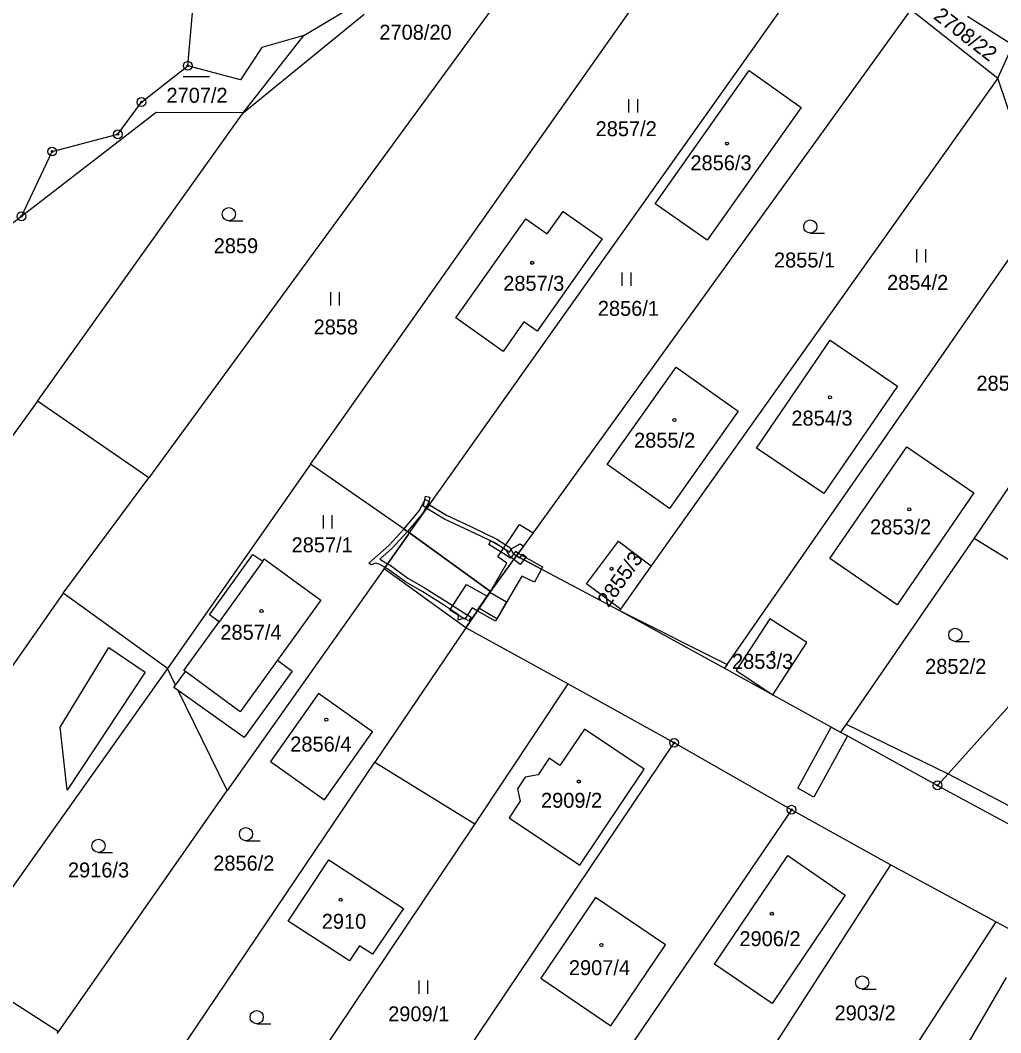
# Model space of a CAD drawing. Extents: x -755819 to -753140, y -1169796 to -1166000.
# Drawn here: x -754138.8 to -754027.3, y -1168813.4 to -1168698.3 of the extents above; entities that cross this region are included whole.
import ezdxf

# ---------------------------------------------------------------- set-up
doc = ezdxf.new("R2010")
doc.units = 0
for name, color, linetype in [('Vrstva 1', 7, 'Continuous'), ('Vrstva 16', 7, 'Continuous'), ('Vrstva 18', 7, 'Continuous'), ('Vrstva 19', 7, 'Continuous'), ('Vrstva 24', 7, 'Continuous'), ('Vrstva 25', 7, 'Continuous'), ('Vrstva 27', 7, 'Continuous'), ('Vrstva 4', 7, 'Continuous'), ('Vrstva 6', 7, 'Continuous')]:
    doc.layers.add(name, color=color, linetype=linetype)

msp = doc.modelspace()

# ---------------------------------------------------------------- linework, layer by layer
at = {"layer": 'Vrstva 1'}
for p, q in [((-754105.8, -1168748.75), (-754061.85, -1168686.4)), ((-754119.75, -1168703.46), (-754118.3, -1168687.42)), ((-754094.54, -1168756.59), (-754046.75, -1168689.25)), ((-754081.72, -1168692.26), (-754124.16, -1168750.33)), ((-754037.53, -1168697.06), (-754082.38, -1168759.2)), ((-754037.53, -1168697.06), (-754027.62, -1168704.86)), ((-754113.45, -1168708.82), (-754099.68, -1168697.61)), ((-754025.93, -1168701.12), (-754031.1, -1168697.87)), ((-754125.01, -1168707.59), (-754119.75, -1168703.46)), ((-754066.6, -1168719.15), (-754055.91, -1168704.01)), ((-754055.91, -1168704.01), (-754049.98, -1168708.21)), ((-754027.62, -1168704.86), (-754053.75, -1168741.61)), ((-754022.59, -1168719.93), (-754027.62, -1168704.86)), ((-754127.7, -1168711.26), (-754125.01, -1168707.59)), ((-754123.33, -1168708.78), (-754138.66, -1168720.59)), ((-754136.85, -1168741.61), (-754113.45, -1168708.82)), ((-754113.45, -1168708.82), (-754123.33, -1168708.78)), ((-754049.98, -1168708.21), (-754060.68, -1168723.31)), ((-754135.16, -1168713.21), (-754127.7, -1168711.26)), ((-754138.66, -1168720.59), (-754135.16, -1168713.21)), ((-754060.68, -1168723.31), (-754066.6, -1168719.15)), ((-754078.89, -1168722.58), (-754077.07, -1168720.02)), ((-754077.07, -1168720.02), (-754072.64, -1168723.16)), ((-754022.59, -1168719.93), (-754042.2, -1168748.18)), ((-754138.66, -1168720.59), (-754146.02, -1168726.26)), ((-754089.25, -1168732.14), (-754081.32, -1168720.86)), ((-754081.32, -1168720.86), (-754078.89, -1168722.58)), ((-754072.64, -1168723.16), (-754080.01, -1168733.66)), ((-754011.92, -1168729.81), (-754030.32, -1168757.19)), ((-754083.88, -1168735.95), (-754089.25, -1168732.14)), ((-754081.52, -1168732.59), (-754083.88, -1168735.95)), ((-754080.01, -1168733.66), (-754081.52, -1168732.59)), ((-754055.06, -1168746.94), (-754046.7, -1168734.65)), ((-754046.7, -1168734.65), (-754039.06, -1168739.88)), ((-754072.04, -1168748.81), (-754064.22, -1168737.74)), ((-754064.22, -1168737.74), (-754057.16, -1168742.74)), ((-754039.06, -1168739.88), (-754047.44, -1168752.12)), ((-754136.85, -1168741.61), (-754192.93, -1168819.06)), ((-754124.16, -1168750.33), (-754136.85, -1168741.61)), ((-754053.75, -1168741.61), (-754067.04, -1168760.31)), ((-754057.16, -1168742.74), (-754064.98, -1168753.81)), ((-754047.44, -1168752.12), (-754055.06, -1168746.94)), ((-754046.75, -1168759.51), (-754037.99, -1168746.78)), ((-754037.99, -1168746.78), (-754030.36, -1168752.02)), ((-754105.8, -1168748.75), (-754122.05, -1168772)), ((-754094.54, -1168756.59), (-754105.8, -1168748.75)), ((-754064.98, -1168753.81), (-754072.04, -1168748.81)), ((-754058.42, -1168771.55), (-754042.2, -1168748.18)), ((-754133.92, -1168763.44), (-754124.16, -1168750.33)), ((-754030.36, -1168752.02), (-754039.1, -1168764.78)), ((-754094.54, -1168756.59), (-754115.25, -1168785.86)), ((-754085.34, -1168763.23), (-754094.54, -1168756.59)), ((-754030.32, -1168757.19), (-754044.9, -1168778.35)), ((-754030.32, -1168757.19), (-754020.27, -1168763.43)), ((-754074.39, -1168762.36), (-754070.76, -1168757.54)), ((-754070.76, -1168757.54), (-754067.04, -1168760.31)), ((-754117.27, -1168765.9), (-754112.33, -1168759.03)), ((-754112.33, -1168759.03), (-754111.23, -1168759.79)), ((-754111.23, -1168759.79), (-754111.05, -1168759.55)), ((-754111.05, -1168759.55), (-754104.62, -1168764.23)), ((-754085.34, -1168763.23), (-754082.38, -1168759.2)), ((-754082.38, -1168759.2), (-754070.67, -1168765.41)), ((-754039.1, -1168764.78), (-754046.75, -1168759.51)), ((-754067.04, -1168760.31), (-754070.56, -1168765.26)), ((-754070.56, -1168765.26), (-754074.39, -1168762.36)), ((-754133.92, -1168763.44), (-754179.64, -1168828.63)), ((-754122.05, -1168772), (-754133.92, -1168763.44)), ((-754104.62, -1168764.23), (-754109.56, -1168771.07)), ((-754088.14, -1168767.36), (-754085.34, -1168763.23)), ((-754070.56, -1168765.26), (-754070.67, -1168765.41)), ((-754116.18, -1168766.68), (-754117.27, -1168765.9)), ((-754070.67, -1168765.41), (-754058.72, -1168771.98)), ((-754053.56, -1168766.35), (-754057.4, -1168772.22)), ((-754049.35, -1168769.06), (-754053.56, -1168766.35)), ((-754016.79, -1168765.59), (-754033.3, -1168783.96)), ((-754120.18, -1168772.24), (-754116.18, -1168766.68)), ((-754088.14, -1168767.36), (-754098.48, -1168782.67)), ((-754076.53, -1168773.73), (-754088.14, -1168767.36)), ((-754053.22, -1168775), (-754049.35, -1168769.06)), ((-754109.56, -1168771.07), (-754107.86, -1168772.31)), ((-754122.05, -1168772), (-754146.05, -1168805.82)), ((-754121.13, -1168773.88), (-754122.05, -1168772)), ((-754120.02, -1168772.35), (-754120.18, -1168772.24)), ((-754058.42, -1168771.55), (-754058.72, -1168771.98)), ((-754058.72, -1168771.98), (-754053.22, -1168775)), ((-754057.4, -1168772.22), (-754053.22, -1168775)), ((-754121.13, -1168773.88), (-754120.02, -1168772.35)), ((-754107.86, -1168772.31), (-754113.34, -1168779.84)), ((-754121.32, -1168774.15), (-754121.13, -1168773.88)), ((-754120.82, -1168774.51), (-754121.32, -1168774.15)), ((-754115.25, -1168785.86), (-754120.82, -1168774.51)), ((-754113.34, -1168779.84), (-754120.82, -1168774.51)), ((-754076.53, -1168773.73), (-754087.1, -1168789.68)), ((-754064.45, -1168780.45), (-754076.53, -1168773.73)), ((-754104.87, -1168774.84), (-754110.34, -1168782.59)), ((-754098.74, -1168779.22), (-754104.87, -1168774.84)), ((-754053.22, -1168775), (-754045.51, -1168779.24)), ((-754074.64, -1168778.89), (-754077.43, -1168783.04)), ((-754067.84, -1168783.44), (-754074.64, -1168778.89)), ((-754044.9, -1168778.35), (-754045.51, -1168779.24)), ((-754104.2, -1168786.94), (-754098.74, -1168779.22)), ((-754045.51, -1168779.24), (-754044.73, -1168779.67)), ((-754044.73, -1168779.67), (-754034.5, -1168785.29)), ((-754101.73, -1168835.9), (-754064.45, -1168780.45)), ((-754051.1, -1168788.06), (-754064.45, -1168780.45)), ((-754110.34, -1168782.59), (-754104.2, -1168786.94)), ((-754078.67, -1168782.21), (-754079.92, -1168784.08)), ((-754077.43, -1168783.04), (-754078.67, -1168782.21)), ((-754123.7, -1168820.03), (-754098.48, -1168782.67)), ((-754075.17, -1168794.38), (-754067.84, -1168783.44)), ((-754081.39, -1168784.35), (-754082.27, -1168785.67)), ((-754079.92, -1168784.08), (-754081.39, -1168784.35)), ((-754033.3, -1168783.96), (-754034.5, -1168785.29)), ((-754134.46, -1168813.33), (-754115.25, -1168785.86)), ((-754082.27, -1168785.67), (-754081.96, -1168787.1)), ((-754034.5, -1168785.29), (-754022.41, -1168791.86)), ((-754081.96, -1168787.1), (-754083.22, -1168788.98)), ((-754051.1, -1168788.06), (-754088.9, -1168843.53)), ((-754039.84, -1168794.33), (-754051.1, -1168788.06)), ((-754083.22, -1168788.98), (-754075.17, -1168794.38)), ((-754087.1, -1168789.68), (-754114.82, -1168830.95)), ((-754108.33, -1168800.74), (-754103.69, -1168793.75)), ((-754103.69, -1168793.75), (-754095.23, -1168799.29)), ((-754059.87, -1168805.63), (-754051.5, -1168793.28)), ((-754051.5, -1168793.28), (-754045, -1168797.79)), ((-754039.84, -1168794.33), (-754075.63, -1168849.92)), ((-754027.85, -1168800.8), (-754039.84, -1168794.33)), ((-754073.38, -1168798.03), (-754079.6, -1168807.22)), ((-754065.41, -1168803.43), (-754073.38, -1168798.03)), ((-754045, -1168797.79), (-754053.3, -1168810.08)), ((-754095.23, -1168799.29), (-754098.73, -1168804.47)), ((-754101.34, -1168805.26), (-754108.33, -1168800.74)), ((-754027.85, -1168800.8), (-754051.69, -1168837.64)), ((-754013.92, -1168808.37), (-754027.85, -1168800.8)), ((-754100.21, -1168803.52), (-754101.34, -1168805.26)), ((-754098.73, -1168804.47), (-754100.21, -1168803.52)), ((-754071.63, -1168812.62), (-754065.41, -1168803.43)), ((-754053.3, -1168810.08), (-754059.87, -1168805.63)), ((-754134.46, -1168813.33), (-754146.05, -1168805.82)), ((-754079.6, -1168807.22), (-754071.63, -1168812.62)), ((-754031.7, -1168815.81), (-754026.65, -1168807.13)), ((-754134.59, -1168813.51), (-754134.46, -1168813.33))]:
    msp.add_line(p, q, dxfattribs=at)
at = {"layer": 'Vrstva 24'}
for centre, radius in [((-754119.75, -1168703.46), 0.5), ((-754119.75, -1168703.46), 0.1), ((-754125.01, -1168707.59), 0.5), ((-754125.01, -1168707.59), 0.1), ((-754127.7, -1168711.26), 0.5), ((-754127.7, -1168711.26), 0.1), ((-754135.16, -1168713.21), 0.5), ((-754135.16, -1168713.21), 0.1), ((-754138.66, -1168720.59), 0.5), ((-754138.66, -1168720.59), 0.1), ((-754064.45, -1168780.45), 0.5), ((-754064.45, -1168780.45), 0.1), ((-754034.5, -1168785.29), 0.5), ((-754034.5, -1168785.29), 0.1), ((-754051.1, -1168788.06), 0.5), ((-754051.1, -1168788.06), 0.1)]:
    msp.add_circle(centre, radius, dxfattribs=at)
at = {"layer": 'Vrstva 25'}
for p, q in [((-754120.27, -1168704.69), (-754117.27, -1168704.69)), ((-754069.58, -1168708.78), (-754069.58, -1168707.28)), ((-754068.58, -1168708.78), (-754068.58, -1168707.28)), ((-754115.07, -1168721.09), (-754113.47, -1168721.09)), ((-754048.96, -1168722.5), (-754047.36, -1168722.5)), ((-754036.84, -1168725.83), (-754036.84, -1168724.33)), ((-754035.84, -1168725.83), (-754035.84, -1168724.33)), ((-754070.34, -1168728.47), (-754070.34, -1168726.97)), ((-754069.34, -1168728.47), (-754069.34, -1168726.97)), ((-754103.49, -1168730.71), (-754103.49, -1168729.21)), ((-754102.49, -1168730.71), (-754102.49, -1168729.21)), ((-754104.32, -1168756.07), (-754104.32, -1168754.57)), ((-754103.32, -1168756.07), (-754103.32, -1168754.57)), ((-754032.47, -1168768.92), (-754030.87, -1168768.92)), ((-754113.13, -1168791.58), (-754111.53, -1168791.58)), ((-754129.9, -1168792.91), (-754128.3, -1168792.91)), ((-754093.44, -1168808.99), (-754093.44, -1168807.49)), ((-754092.44, -1168808.99), (-754092.44, -1168807.49)), ((-754043.07, -1168808.45), (-754041.47, -1168808.45)), ((-754111.91, -1168812.4), (-754110.31, -1168812.4))]:
    msp.add_line(p, q, dxfattribs=at)
for centre, radius in [((-754058.42, -1168712.31), 0.175), ((-754115.07, -1168720.34), 0.75), ((-754048.96, -1168721.75), 0.75), ((-754080.59, -1168725.87), 0.175), ((-754046.72, -1168741.17), 0.175), ((-754064.42, -1168743.74), 0.175), ((-754037.71, -1168753.91), 0.175), ((-754071.56, -1168760.67), 0.175), ((-754111.36, -1168765.47), 0.175), ((-754032.47, -1168768.17), 0.75), ((-754053.23, -1168770.22), 0.175), ((-754104, -1168777.82), 0.175), ((-754075.28, -1168784.85), 0.175), ((-754113.13, -1168790.83), 0.75), ((-754129.9, -1168792.16), 0.75), ((-754102.36, -1168798.3), 0.175), ((-754053.33, -1168799.89), 0.175), ((-754072.72, -1168803.44), 0.175), ((-754043.07, -1168807.7), 0.75), ((-754111.91, -1168811.65), 0.75)]:
    msp.add_circle(centre, radius, dxfattribs=at)
at = {"layer": 'Vrstva 27'}
for p, q in [((-754092.95, -1168753.54), (-754092.73, -1168752.42)), ((-754092.73, -1168752.42), (-754092.24, -1168752.51)), ((-754092.24, -1168752.51), (-754092.39, -1168753.3)), ((-754093.45, -1168754.07), (-754092.75, -1168752.78)), ((-754092.31, -1168753.02), (-754093.03, -1168754.35)), ((-754092.55, -1168753.79), (-754092.95, -1168753.54)), ((-754092.75, -1168752.78), (-754092.31, -1168753.02)), ((-754092.26, -1168753.38), (-754092.55, -1168753.79)), ((-754092.55, -1168753.79), (-754092.26, -1168753.38)), ((-754090.55, -1168755.02), (-754092.55, -1168753.79)), ((-754092.39, -1168753.3), (-754092.26, -1168753.38)), ((-754092.26, -1168753.38), (-754090.31, -1168754.58)), ((-754095.18, -1168756.15), (-754093.45, -1168754.07)), ((-754093.03, -1168754.35), (-754094.77, -1168756.43)), ((-754087.71, -1168756.35), (-754090.55, -1168755.02)), ((-754090.31, -1168754.58), (-754087.49, -1168755.89)), ((-754096.86, -1168757.97), (-754095.18, -1168756.15)), ((-754095.18, -1168756.15), (-754094.77, -1168756.43)), ((-754094.77, -1168756.43), (-754095.18, -1168756.15)), ((-754087.49, -1168755.89), (-754084.59, -1168757.29)), ((-754084.5, -1168759.29), (-754082.02, -1168755.61)), ((-754082.02, -1168755.61), (-754080.47, -1168756.56)), ((-754097.43, -1168760.67), (-754094.54, -1168756.59)), ((-754094.77, -1168756.43), (-754096.52, -1168758.33)), ((-754094.54, -1168756.59), (-754085.34, -1168763.23)), ((-754084.83, -1168757.73), (-754087.71, -1168756.35)), ((-754084.59, -1168757.29), (-754083.13, -1168758.24)), ((-754080.47, -1168756.56), (-754082.16, -1168758.9)), ((-754099.17, -1168760.02), (-754096.86, -1168757.97)), ((-754096.52, -1168758.33), (-754097.91, -1168759.57)), ((-754085.53, -1168757.91), (-754085.27, -1168757.48)), ((-754083.79, -1168758.95), (-754085.53, -1168757.91)), ((-754085.27, -1168757.48), (-754083.7, -1168758.41)), ((-754083.51, -1168758.6), (-754084.83, -1168757.73)), ((-754083.7, -1168758.41), (-754083.18, -1168758.76)), ((-754083.18, -1168758.76), (-754082.9, -1168758.35)), ((-754083.13, -1168758.24), (-754082.74, -1168758.92)), ((-754082.9, -1168758.35), (-754081.94, -1168757.84)), ((-754081.58, -1168758.1), (-754082.16, -1168758.9)), ((-754081.94, -1168757.84), (-754081.58, -1168758.1)), ((-754097.91, -1168759.57), (-754097.02, -1168760.09)), ((-754082.16, -1168758.9), (-754085.34, -1168763.23)), ((-754085.34, -1168763.23), (-754082.38, -1168759.2)), ((-754083.48, -1168760.04), (-754084.5, -1168759.29)), ((-754083.04, -1168759.46), (-754083.79, -1168758.95)), ((-754083.12, -1168759.26), (-754083.51, -1168758.6)), ((-754082.68, -1168759.61), (-754083.12, -1168759.26)), ((-754082.47, -1168758.68), (-754083.04, -1168759.46)), ((-754082.74, -1168758.92), (-754082.38, -1168759.2)), ((-754082.68, -1168759.61), (-754082.38, -1168759.2)), ((-754082.38, -1168759.2), (-754082.68, -1168759.61)), ((-754081.95, -1168760.18), (-754082.68, -1168759.61)), ((-754082.16, -1168758.9), (-754082.47, -1168758.68)), ((-754082.38, -1168759.2), (-754082.16, -1168758.9)), ((-754082.38, -1168759.2), (-754081.98, -1168759.41)), ((-754079.54, -1168760.71), (-754082.38, -1168759.2)), ((-754082.38, -1168759.2), (-754079.54, -1168760.71)), ((-754082.16, -1168758.9), (-754079.41, -1168760.45)), ((-754081.98, -1168759.41), (-754081.66, -1168759)), ((-754081.53, -1168759.65), (-754081.98, -1168759.41)), ((-754081.98, -1168759.41), (-754081.53, -1168759.65)), ((-754081.66, -1168759), (-754081.26, -1168759.31)), ((-754081.26, -1168759.31), (-754081.53, -1168759.65)), ((-754098.89, -1168760.23), (-754099.17, -1168760.02)), ((-754098.35, -1168760.01), (-754098.89, -1168760.23)), ((-754097.89, -1168760.16), (-754098.35, -1168760.01)), ((-754097.31, -1168760.5), (-754097.89, -1168760.16)), ((-754088.14, -1168767.36), (-754097.43, -1168760.67)), ((-754097.31, -1168760.5), (-754097.02, -1168760.09)), ((-754097.02, -1168760.09), (-754097.31, -1168760.5)), ((-754097.03, -1168760.67), (-754097.31, -1168760.5)), ((-754095, -1168762.14), (-754097.03, -1168760.67)), ((-754097.02, -1168760.09), (-754096.75, -1168760.25)), ((-754096.75, -1168760.25), (-754094.72, -1168761.72)), ((-754085.34, -1168763.23), (-754083.48, -1168760.04)), ((-754081.53, -1168759.65), (-754081.95, -1168760.18)), ((-754079.54, -1168760.71), (-754080.33, -1168762.2)), ((-754079.41, -1168760.45), (-754079.54, -1168760.71)), ((-754094.72, -1168761.72), (-754092.76, -1168762.85)), ((-754081.76, -1168761.51), (-754084.6, -1168766.37)), ((-754080.33, -1168762.2), (-754081.76, -1168761.51)), ((-754093.02, -1168763.27), (-754095, -1168762.14)), ((-754092.76, -1168762.85), (-754090.39, -1168764.36)), ((-754089.94, -1168765.36), (-754088.07, -1168762.46)), ((-754088.07, -1168762.46), (-754085.71, -1168763.78)), ((-754090.67, -1168764.78), (-754093.02, -1168763.27)), ((-754085.34, -1168763.23), (-754088.14, -1168767.36)), ((-754085.71, -1168763.78), (-754086.84, -1168765.44)), ((-754086.64, -1168765.14), (-754085.34, -1168763.23)), ((-754086.64, -1168765.14), (-754085.71, -1168763.78)), ((-754085.71, -1168763.78), (-754085.41, -1168763.33)), ((-754085.41, -1168763.33), (-754083.51, -1168764.41)), ((-754088.97, -1168765.91), (-754090.67, -1168764.78)), ((-754090.39, -1168764.36), (-754088.28, -1168765.71)), ((-754088.24, -1168766.41), (-754089.94, -1168765.36)), ((-754087.41, -1168765.12), (-754088.24, -1168766.41)), ((-754086.84, -1168765.44), (-754087.41, -1168765.12)), ((-754086.84, -1168765.44), (-754086.64, -1168765.14)), ((-754084.6, -1168766.37), (-754086.64, -1168765.14)), ((-754083.51, -1168764.41), (-754084.75, -1168766.62)), ((-754089, -1168766.52), (-754088.97, -1168765.91)), ((-754088.32, -1168766.27), (-754089, -1168766.52)), ((-754087.78, -1168766.59), (-754088.32, -1168766.27)), ((-754088.28, -1168765.71), (-754087.52, -1168766.16)), ((-754087.52, -1168766.16), (-754087.78, -1168766.59)), ((-754084.75, -1168766.62), (-754086.84, -1168765.44)), ((-754050.38, -1168785.61), (-754046.57, -1168778.66)), ((-754046.57, -1168778.66), (-754045.51, -1168779.24)), ((-754044.73, -1168779.67), (-754048.54, -1168786.62)), ((-754045.51, -1168779.24), (-754044.73, -1168779.67)), ((-754048.54, -1168786.62), (-754050.38, -1168785.61))]:
    msp.add_line(p, q, dxfattribs=at)
at = {"layer": 'Vrstva 4'}
for p, q in [((-754111.23, -1168759.79), (-754116.18, -1168766.68)), ((-754070.67, -1168765.41), (-754058.42, -1168771.55)), ((-754134.26, -1168778.68), (-754128.73, -1168769.63)), ((-754128.73, -1168769.63), (-754124.58, -1168772.42)), ((-754109.56, -1168771.07), (-754113.79, -1168776.93)), ((-754124.58, -1168772.42), (-754133.45, -1168785.84)), ((-754113.79, -1168776.93), (-754120.02, -1168772.35)), ((-754133.45, -1168785.84), (-754134.26, -1168778.68)), ((-754044.9, -1168778.35), (-754033.3, -1168783.96)), ((-754098.48, -1168782.67), (-754087.1, -1168789.68)), ((-754033.3, -1168783.96), (-754021.04, -1168790.4))]:
    msp.add_line(p, q, dxfattribs=at)
at = {"layer": 'Vrstva 6'}
for p, q in [((-754106.54, -1168700.02), (-754091.05, -1168690.72)), ((-754113.45, -1168708.82), (-754106.54, -1168700.02)), ((-754106.54, -1168700.02), (-754111.31, -1168701.39)), ((-754111.31, -1168701.39), (-754113.76, -1168705.06)), ((-754027.62, -1168704.86), (-754025.93, -1168701.12)), ((-754113.76, -1168705.06), (-754119.75, -1168703.46))]:
    msp.add_line(p, q, dxfattribs=at)

# ---------------------------------------------------------------- texts
at = {"layer": 'Vrstva 16'}
msp.add_text('2708/20', height=1.7, dxfattribs=at).set_placement((-754097.96, -1168700.5))
at = {"layer": 'Vrstva 18'}
msp.add_text('2708/22', height=1.7, rotation=322.1742, dxfattribs=at).set_placement((-754035.06, -1168698.03))
for s, p in [('2707/2', (-754122.17, -1168707.67)), ('2857/2', (-754073.37, -1168711.47)), ('2859', (-754116.8, -1168724.78)), ('2855/1', (-754053.09, -1168726.4)), ('2854/2', (-754040.23, -1168728.95)), ('2856/1', (-754073.12, -1168731.9)), ('2858', (-754105.44, -1168734.01)), ('2853/1', (-754030.07, -1168740.41)), ('2857/1', (-754107.94, -1168758.79)), ('2852/2', (-754035.9, -1168772.61)), ('2916/3', (-754133.37, -1168795.76)), ('2856/2', (-754116.85, -1168794.98)), ('2903/2', (-754046.2, -1168812.01)), ('2909/1', (-754096.96, -1168812.12))]:
    msp.add_text(s, height=1.7, dxfattribs=at).set_placement(p)
at = {"layer": 'Vrstva 19'}
for s, p in [('2856/3', (-754062.59, -1168715.35)), ('2857/3', (-754083.88, -1168729.05)), ('2854/3', (-754051.11, -1168744.38)), ('2855/2', (-754069, -1168746.89)), ('2853/2', (-754042.17, -1168756.75)), ('2857/4', (-754116.04, -1168768.73)), ('2853/3', (-754057.86, -1168772.04)), ('2856/4', (-754108.09, -1168781.44)), ('2909/2', (-754079.58, -1168787.84)), ('2910', (-754104.51, -1168801.6)), ('2906/2', (-754057.02, -1168803.57)), ('2907/4', (-754076.41, -1168806.87))]:
    msp.add_text(s, height=1.7, dxfattribs=at).set_placement(p)
msp.add_text('2855/3', height=1.7, rotation=54.7748, dxfattribs=at).set_placement((-754071.91, -1168765.16))

doc.saveas('drawing.dxf')
